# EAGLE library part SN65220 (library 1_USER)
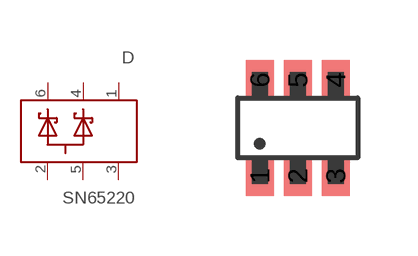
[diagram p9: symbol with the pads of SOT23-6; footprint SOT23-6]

Designator prefix D

## SN65220  [SOT23-6]
1  NC_1  pas
2  GND_2  pas
3  NC_3  pas
4  B  pas
5  GND_5  pas
6  A  pas

## Footprint SOT23-6 (pad centres in mm)
smd 0.7 x 1: 1 -0.95,-1.2; 2 0,-1.2; 3 0.95,-1.2; 4 0.95,1.2; 5 0,1.2; 6 -0.95,1.2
